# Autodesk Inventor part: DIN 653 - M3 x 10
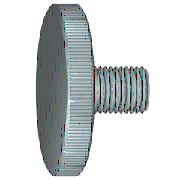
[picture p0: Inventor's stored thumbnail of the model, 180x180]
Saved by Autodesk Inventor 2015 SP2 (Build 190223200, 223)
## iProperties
Created: 2012-02
Part Number: DIN 653 - M3 x 10
Material: Stahl, weich
Description: Rändelschraube
Document SubType Name: Modeling
Standard: DIN 653
Designer: rYan
Standards Organization: DIN
Language: de-DE
Size Designation: M3 x 10
Categories: <MemberInstance><Categories><Category DisplayName="Verbindungselemente" InternalName="e4da775c-781d-43d5-af7c-5136215cf5a6" Mnemonic="FSTN"><Category DisplayNam
Density: 7.85 g/cm^3
Appearance: Halbpoliert
IsCustomPart: 0
Author: rYan
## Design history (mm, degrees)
revolve "Körper" stored, may be unused: angle "d8" = 90 deg
node "IDS_WORKPLANE{1}"
workplane "Work Plane2"
body "Solid1"
feature "Gewinde" dims "d2" = 8.224 (= GEL - 0.092 x GD), "d3" = 0
chamfer "Fase1" distance "d10" = 0.3 (= PHH); stored, may be unused: angle "d11" = 45 deg (= FAWI), second distance "d38" = 0.3 (= PHH)
sketch "Skizze1"
  geometry: L1 (-2.5, 0)-(10, 0); L2 (10, 0)-(10, 5); L3 (9.673, 1.5)-(0, 1.5); L4 (0, -1.2)-(0, 7.2) reference; L5 (0, 1.5)-(0, 6); L6 (0, 6)-(-2.5, 6); L7 (-2.5, 6)-(-2.5, 0); L8 (-5.016, 0)-(12.597, 0) reference; A1 r 3.6 centre (6.4, 0) between (10, 0) and (9.673, 1.5)
  constraints: 13 end point, 2 perpendicular, 2 point on circle, 2 vertical alignment, 1 centre point, 1 collinear, 1 parallel, 1 point on line, 1 tangent
  dimensions: "d1" = 3 diameter of L3 L1 (= GD); "d6" = 12 diameter of L6 L1 (= KOD); "d7" = 2.5 distance between parallel lines of L5 L7 (= KOH); "d9" = 3.6 radius of A1 (= 1.2 x GD); "d41" = 10 distance between parallel lines of L2 L5 (= NLG)
other parameters: "GD" = 3 [user parameter; used in 3 equation terms], "NLG" = 10 [user parameter; used in 1 equation term], "GEL" = 8.5 [user parameter; used in 1 equation term], "KOD" = 12 [user parameter; used in 1 equation term], "KOH" = 2.5 [user parameter; used in 2 equation terms], "GAL" = 0.30673 (= 0.61345 x PTC) [user parameter], "d4" = 0, "SD" = 0 [user parameter], "LADI" = 3 (= NND) [user parameter], "PHH" = 0.3 [user parameter; used in 2 equation terms], "FAWI" = 45 deg [user parameter; used in 1 equation term], "d12" = -1.25 (= -0.5 x KOH), "T" = 0.5 [user parameter], "d39" = 0, "d42" = 0, "NND" = 3 [user parameter; used in 1 equation term], "PTC" = 0.5 [user parameter; used in 2 equation terms]
